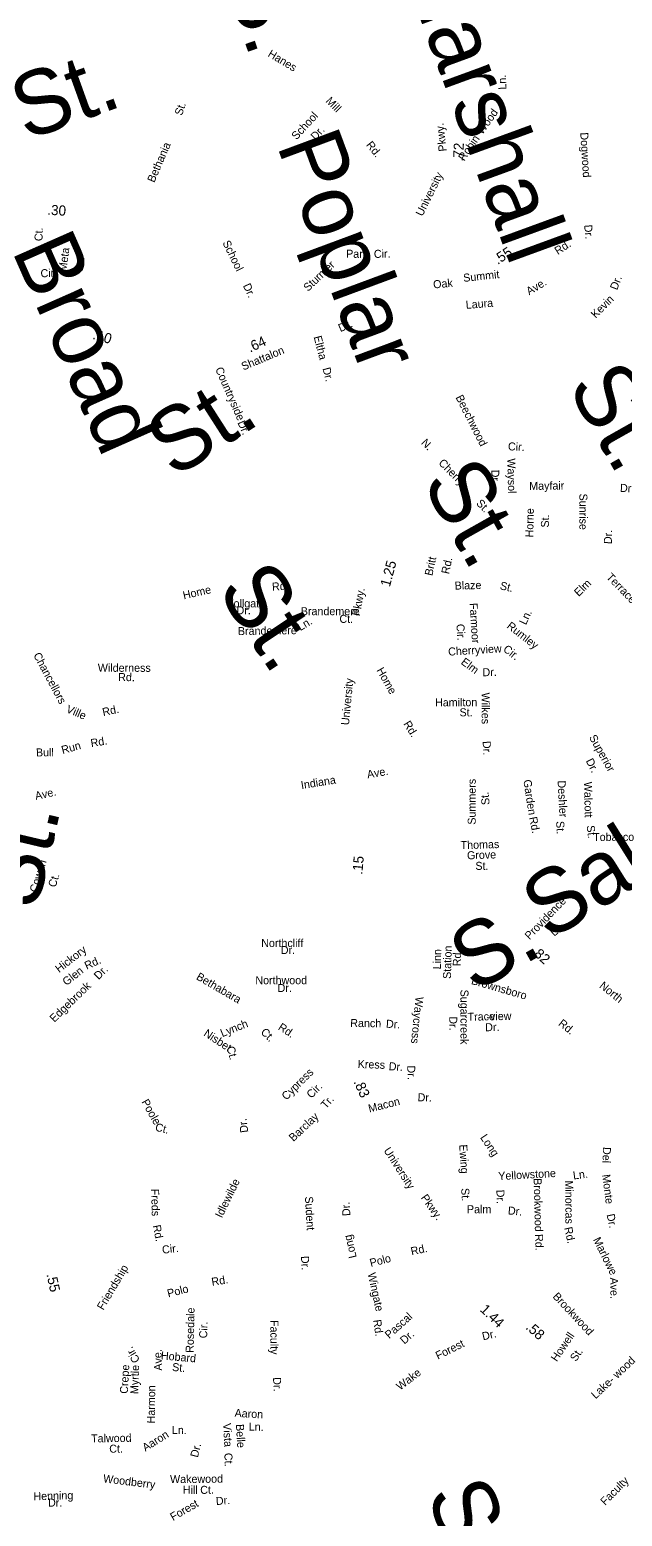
# Model space of a CAD drawing. Extents: x 1553981 to 1780076, y 812965 to 996873.
# Drawn here: x 1631790 to 1632669, y 849777 to 851982 of the extents above; entities that cross this region are included whole.
import ezdxf

# ---------------------------------------------------------------- set-up
doc = ezdxf.new("R2010")
doc.units = 0
for name, color, linetype in [('Exist Road Non-System Type 51 Label', 7, 'Continuous'), ('Exist Road Secondary Mileage Hundredths English Label', 7, 'Continuous'), ('Map Preparation Border Antique Large Shape', 7, 'Continuous')]:
    doc.layers.add(name, color=color, linetype=linetype)

msp = doc.modelspace()

# ---------------------------------------------------------------- texts
at = {"layer": 'Exist Road Non-System Type 51 Label'}
for s, height, rotation, p in [('Marshall', 95, 290.0731, (1632339.3, 852080.3)), ('S.', 95, 288.9209, (1632078.6, 852052.4)), ('St.', 95, 19.7887, (1631783.9, 851817.6)), ('Hanes', 11.88, 329.1772, (1632142.1, 851943.5)), ('Ln.', 11.88, 92.0969, (1632497.3, 851893.8)), ('Mill', 11.88, 314.3448, (1632228.2, 851875.9)), ('School', 11.88, 47.1963, (1632185.6, 851818.2)), ('Wood', 11.88, 54.5217, (1632461.4, 851826)), ('Poplar', 95, 290.3707, (1632155.9, 851811.4)), ('Dr.', 11.88, 47.1963, (1632214.1, 851817.6)), ('Robin', 11.88, 55.4105, (1632434.5, 851786.8)), ('Dogwood', 11.88, 273.5931, (1632606.7, 851829.8)), ('Rd.', 11.88, 308.572, (1632288.3, 851811.3)), ('Dr.', 11.88, 275.0819, (1632612.5, 851692.7)), ('Broad', 95, 293.8107, (1631762.5, 851655.3)), ('Ct.', 11.88, 88.6998, (1631808.7, 851668.7)), ('School', 11.88, 295.9309, (1632075.5, 851666.5)), ('Meta', 11.87, 82.6531, (1631844.2, 851623.4)), ('Park', 11.88, 358.6211, (1632259.2, 851644.4)), ('Cir.', 11.87, 1.352, (1632300.6, 851643.9)), ('Cir.', 11.88, 1.981, (1631806, 851615.1)), ('Dr.', 11.87, 82.6531, (1631868.6, 851623.9)), ('Sturmer', 11.87, 43.5499, (1632202.7, 851593.4)), ('Dr.', 11.88, 294.7328, (1632105.9, 851602.9)), ('Ave.', 11.88, 31.125, (1632531, 851588.3)), ('Dr.', 11.88, 68.9622, (1632661.4, 851595.4)), ('Laura', 11.88, 4.4816, (1632437.3, 851568.3)), ('Kevin', 11.88, 45.1038, (1632629.6, 851553.5)), ('Eltha', 11.88, 284.6129, (1632211, 851526.8)), ('Countryside', 11.875, 293.5159, (1632064.8, 851479)), ('Dr.', 11.88, 284.4327, (1632224.1, 851479.9)), ('St.', 95, 299.4456, (1632586.6, 851453.7)), ('St.', 95, 32.6529, (1632003.6, 851315.9)), ('Beechwood', 11.87, 296.8338, (1632421.4, 851437.1)), ('Dr.', 11.88, 293.5159, (1632097.8, 851399.6)), ('N.', 11.88, 313.7502, (1632369.8, 851368.8)), ('Cir.', 11.88, 357.2843, (1632499.3, 851358.6)), ('St.', 95, 299.3634, (1632370.8, 851311)), ('Cherry', 11.88, 314.6983, (1632395.6, 851338.8)), ('Waysol', 11.87, 271.3693, (1632498.5, 851346.4)), ('Dr.', 11.87, 271.3693, (1632474.7, 851329.6)), ('Mayfair', 11.88, 0.7722, (1632531.1, 851299.7)), ('Sunrise', 11.88, 270.0227, (1632605.5, 851294.3)), ('Dr.', 11.88, 356.8408, (1632665.5, 851297)), ('St.', 11.87, 313.7565, (1632451.5, 851279.1)), ('Horne', 11.88, 88.8359, (1632537, 851229.2)), ('St.', 11.88, 88.8359, (1632560.2, 851243.8)), ('Dr.', 11.88, 88.7027, (1632653.6, 851219.3)), ('St.', 95, 303.5775, (1632066.3, 851151.3)), ('Britt', 11.88, 77.8365, (1632387.2, 851171.6)), ('Rd.', 11.88, 77.8365, (1632411.9, 851174.2)), ('Rd.', 11.88, 3.9423, (1632149.7, 851150.2)), ('Blaze', 11.88, 1.3863, (1632420.5, 851151.8)), ('St.', 11.87, 346.8364, (1632486.8, 851152.5)), ('Elm', 11.88, 44.4001, (1632604.5, 851140.8)), ('Terrace', 11.88, 314.3249, (1632644.5, 851169.5)), ('Home', 11.88, 12.8534, (1632018.5, 851137.3)), ('Farmoor', 11.88, 273.585, (1632442.4, 851131.7)), ('Ln.', 11.88, 64.6535, (1632526.1, 851098.6)), ('Brandemere', 11.87, 0.9828, (1632098.8, 851084.3)), ('Ln.', 11.88, 31.008, (1632191.4, 851090.2)), ('Cir.', 11.88, 273.585, (1632422.9, 851100.6)), ('Rumley', 11.88, 321.912, (1632496.7, 851095.9)), ('Chancellors', 11.875, 298.1893, (1631794.7, 851054.7)), ('Cherryview', 11.88, 3.5763, (1632411.1, 851053.8)), ('Elm', 11.88, 323.5526, (1632428.7, 851042.3)), ('Cir.', 11.88, 321.912, (1632491.3, 851061.6)), ('Wilderness', 11.88, 359.9777, (1631890.8, 851029.9)), ('Rd.', 11.88, 359.4648, (1631921, 851016.2)), ('Home', 11.87, 299.2616, (1632304, 851032.3)), ('Dr.', 11.88, 1.2876, (1632461.8, 851023.3)), ('Hamilton', 11.88, 0.3871, (1632391.3, 850978.5)), ('Wilkes', 11.88, 270.1647, (1632460.4, 850999.1)), ('Ville', 11.88, 336.976, (1631842.9, 850970.2)), ('Rd.', 11.88, 11.9842, (1631898.9, 850964.1)), ('St.', 11.88, 359.8069, (1632427.6, 850963.9)), ('Rd.', 11.88, 302.2274, (1632343.8, 850952.6)), ('Run', 11.88, 15.5803, (1631838.6, 850907.8)), ('Rd.', 11.88, 9.4506, (1631881.1, 850918.1)), ('Dr.', 11.87, 272.1303, (1632462, 850927.1)), ('Superior', 11.88, 299.1661, (1632619.4, 850932.6)), ('Bull', 11.88, 0.6233, (1631799.1, 850904.3)), ('Dr.', 11.88, 296.9846, (1632614.6, 850897.8)), ('Ave.', 11.87, 9.867, (1632291.3, 850871.7)), ('Salem', 95, 32.0713, (1632560.3, 850629.9)), ('Ave.', 11.87, 12.215, (1631798.9, 850839.8)), ('Indiana', 11.88, 9.3345, (1632193.2, 850855.8)), ('Summers', 11.88, 89.9293, (1632451.6, 850803.1)), ('Garden', 11.88, 278.5777, (1632522.3, 850869.1)), ('Deshler', 11.88, 273.0208, (1632573.1, 850868.4)), ('Walcott', 11.87, 271.1338, (1632612.4, 850866.7)), ('St.', 11.88, 94.7168, (1632472.3, 850832.7)), ('St.', 95, 76.7191, (1631800.2, 850674.3)), ('Rd.', 11.88, 281.4454, (1632530.8, 850813.7)), ('St.', 11.88, 273.0208, (1632571, 850808.2)), ('St.', 11.88, 276.0666, (1632616.3, 850801.6)), ('Tobacco', 11.88, 0.1113, (1632625.9, 850778.9)), ('Thomas', 11.88, 1.7498, (1632429.4, 850766.7)), ('Grove', 11.87, 1.9621, (1632438.9, 850751.6)), ('Cowan', 11.88, 73.0536, (1631800.5, 850701.7)), ('St.', 11.88, 359.7356, (1632451.1, 850736.1)), ('Ct.', 11.88, 73.0536, (1631828.1, 850709.3)), ('Providence', 11.88, 46.0097, (1632531.5, 850631.7)), ('S.', 95, 29.4841, (1632449.3, 850553.1)), ('Ln.', 11.88, 43.5543, (1632568.4, 850636.7)), ('Hickory', 11.88, 37.6686, (1631833.3, 850582.9)), ('Linn', 11.88, 89.365, (1632400.1, 850588.4)), ('Station', 11.87, 88.4573, (1632414.8, 850574.2)), ('Rd.', 11.88, 88.2955, (1632429.4, 850593)), ('Glen', 11.88, 37.6686, (1631844, 850563.6)), ('Rd.', 11.88, 24.3572, (1631874.3, 850587.8)), ('Dr.', 11.88, 45.0238, (1631892, 850572.3)), ('Edgebrook', 11.88, 44.0894, (1631826.3, 850509.1)), ('Bethabara', 11.88, 329.7861, (1632035.8, 850574.3)), ('Brownsboro', 11.88, 343.9261, (1632444.1, 850566.9)), ('Waycross', 11.88, 264.3614, (1632362.4, 850548.2)), ('Sugarcreek', 11.88, 270, (1632429, 850558.4)), ('Trace', 11.88, 1.5706, (1632439.7, 850512)), ('-view', 11.88, 1.5706, (1632467.7, 850512.6)), ('Nisbet', 11.88, 326.378, (1632046.8, 850490.8)), ('Lynch', 11.88, 21.6817, (1632075.5, 850487.8)), ('Ct.', 11.88, 315.0536, (1632131.6, 850494.4)), ('Rd.', 11.88, 326.9359, (1632157.3, 850499.8)), ('Ranch', 11.88, 359.3395, (1632265.4, 850503)), ('Dr.', 11.88, 356.4137, (1632318.2, 850502)), ('Dr.', 11.88, 270, (1632412.4, 850518.8)), ('Dr.', 11.88, 1.5706, (1632465.8, 850496.6)), ('Rd.', 11.88, 321.093, (1632573.3, 850506.4)), ('Ct.', 11.88, 285.0324, (1632081.9, 850472.7)), ('Cypress', 11.88, 44.7704, (1632170.6, 850393.6)), ('Kress', 11.88, 358.0523, (1632276.3, 850442.2)), ('Dr.', 11.88, 355.8421, (1632322.2, 850439)), ('Dr.', 11.88, 272.8109, (1632349.8, 850445.6)), ('Cir.', 11.88, 44.7704, (1632207.6, 850396.2)), ('Poole', 11.88, 299.4574, (1631955.1, 850391.8)), ('Tr.', 11.88, 48.5515, (1632229.4, 850380.7)), ('Macon', 11.88, 13.9788, (1632293.8, 850376)), ('Dr.', 11.87, 358.3414, (1632365.3, 850392.9)), ('Barclay', 11.88, 43.2972, (1632181.1, 850332.2)), ('Ct.', 11.88, 345.9534, (1631975.1, 850349.3)), ('Dr.', 11.88, 97.7033, (1632114.2, 850346.9)), ('Ewing', 11.88, 273.6356, (1632427.1, 850328.3)), ('Long', 11.88, 303.4806, (1632457.7, 850339)), ('Del', 11.88, 267.9499, (1632640.5, 850325.1)), ('Yellowstone', 11.875, 3.1299, (1632485.4, 850275.8)), ('Ln.', 11.88, 7.333, (1632596.7, 850276.7)), ('Monte', 11.88, 277.2707, (1632639.2, 850283.6)), ('Freds', 11.87, 271.743, (1631969.8, 850262.7)), ('Idlewilde', 11.88, 63.9916, (1632074.9, 850218.7)), ('St.', 11.87, 273.6985, (1632430, 850263.6)), ('Dr.', 11.88, 271.889, (1632482.3, 850261.4)), ('Brookwood', 11.88, 271.4872, (1632537.5, 850278.5)), ('Minorcas', 11.87, 270.4993, (1632584.3, 850275.2)), ('Sudent', 11.87, 273.1563, (1632198.2, 850251.3)), ('Dr.', 11.88, 94.0847, (1632265.8, 850222.9)), ('Dr.', 11.88, 94.0847, (1632265.8, 850222.9)), ('Palm', 11.88, 359.9382, (1632438.6, 850226.7)), ('Dr.', 11.88, 354.9025, (1632499, 850225)), ('Dr.', 11.88, 281.9057, (1632645.8, 850224.5)), ('Rd.', 11.88, 281.3468, (1631972.2, 850208.2)), ('Long', 11.88, 103.4813, (1632275.1, 850161.4)), ('Rd.', 11.88, 272.1643, (1632539.6, 850195.6)), ('Rd.', 11.88, 282.3111, (1632582.9, 850205)), ('Marlowe', 11.88, 296.2202, (1632625.4, 850187.5)), ('Cir.', 11.88, 6.3242, (1631986.8, 850166.5)), ('Rd.', 11.88, 12.5206, (1632356.6, 850164.1)), ('Friendship', 11.88, 59.3908, (1631898.9, 850082)), ('Dr.', 11.88, 273.5264, (1632192.2, 850163)), ('Polo', 11.88, 14.4063, (1632296, 850146.9)), ('Rd.', 11.88, 9.5609, (1632060.5, 850118.8)), ('Wingate', 11.88, 282.3504, (1632291.2, 850137.1)), ('Ave.', 11.87, 271.2385, (1632651, 850131.2)), ('Polo', 11.88, 14.4537, (1631995.5, 850101.6)), ('Brookwood', 11.88, 313.1198, (1632565, 850102.4)), ('Rosedale', 11.87, 88.694, (1632032.9, 850019.5)), ('Pascal', 11.87, 41.9455, (1632323.2, 850039.8)), ('Cir.', 11.88, 88.513, (1632053, 850041)), ('Faculty', 11.88, 270.0081, (1632146.9, 850068.3)), ('Rd.', 11.88, 278.0148, (1632299.4, 850068.1)), ('Dr.', 11.87, 41.9455, (1632345.8, 850031.6)), ('Forest', 11.88, 26.453, (1632395.6, 850009.3)), ('Dr.', 11.88, 13.3882, (1632462.6, 850038)), ('Howell', 11.88, 55.8999, (1632572, 850005.5)), ('Cir.', 11.88, 120.4051, (1631953.9, 850008.7)), ('Ave.', 11.87, 91.6542, (1631986.2, 849993.3)), ('Hobard', 11.88, 354.998, (1631984.1, 850009.9)), ('St.', 11.88, 55.8999, (1632600.4, 850005.7)), ('Lake- wood', 11.88, 43.2531, (1632629.6, 849950.4)), ('Crepe', 11.88, 87.0067, (1631935.3, 849958.6)), ('Myrtle', 11.88, 88.2238, (1631950.8, 849958.2)), ('St.', 11.88, 354.998, (1632000.7, 849992.8)), ('Wake', 11.88, 37.4427, (1632339.4, 849963.3)), ('Harmon', 11.88, 89.3908, (1631975.5, 849914.8)), ('Dr.', 11.87, 273.1886, (1632150.7, 849983.1)), ('Aaron', 11.88, 356.5392, (1632093.5, 849924.7)), ('Ln.', 11.88, 359.3608, (1632000.7, 849899.2)), ('Vista', 11.88, 273.4986, (1632076.6, 849914.9)), ('Belle', 11.88, 273.4986, (1632095.7, 849913.5)), ('Ln.', 11.88, 358.3172, (1632114.6, 849904.3)), ('Talwood', 11.88, 0.8749, (1631880.9, 849886.6)), ('Ct.', 11.87, 0.3328, (1631907.8, 849871.4)), ('Aaron', 11.88, 32.0258, (1631961.4, 849872.8)), ('Dr.', 11.88, 75.7872, (1632039.2, 849863.5)), ('Ct.', 11.87, 272.3682, (1632078.5, 849870.9)), ('Woodberry', 11.88, 353.006, (1631898.2, 849827.5)), ('Wakewood', 11.87, 0.5589, (1631998.1, 849826.2)), ('Hill', 11.88, 359.3962, (1632016.9, 849810.5)), ('Ct.', 11.88, 1.0575, (1632042.9, 849810.2)), ('S.', 95, 291.6458, (1632377.6, 849809.8)), ('Faculty', 11.88, 45.0998, (1632643.6, 849792.4)), ('Henning', 11.88, 1.7039, (1631795.4, 849800.7)), ('Dr.', 11.87, 359.9641, (1631816.9, 849791.4)), ('Forest', 11.88, 30.0904, (1632002.4, 849769.9)), ('Dr.', 11.88, 4.1908, (1632066.4, 849793.7))]:
    msp.add_text(s, height=height, rotation=rotation, dxfattribs=at).set_placement(p)
for s, p in [('Tollgate', (1632082.6, 851125.5)), ('Dr.', (1632096.7, 851115.2)), ('Brandemere', (1632192, 851113.9)), ('Ct.', (1632249.4, 851102.5)), ('Northcliff', (1632133.3, 850621.6)), ('Dr.', (1632162.3, 850611.2)), ('Northwood', (1632124.6, 850566.4)), ('Dr.', (1632157.6, 850554.9))]:
    msp.add_text(s, height=11.88, dxfattribs=at).set_placement(p)
at = {"layer": 'Exist Road Secondary Mileage Hundredths English Label'}
for s, rotation, p in [('.72', 87.4072, (1632432.9, 851786.6)), ('.30', 356.5146, (1631815.4, 851708.1)), ('.55', 33.4435, (1632484.2, 851633.5)), ('.10', 343.9485, (1631882.2, 851523.9)), ('.64', 24.5204, (1632116.8, 851503.4)), ('1.25', 74.8646, (1632324.1, 851154.9)), ('.15', 85.2092, (1632283.3, 850728.4)), ('.82', 318.3729, (1632532.9, 850613.3)), ('.83', 294.4943, (1632270, 850421.7)), ('.55', 282.4529, (1631814.5, 850135.8)), ('1.44', 316.2346, (1632457, 850082.5)), ('.58', 318.523, (1632524.8, 850056))]:
    msp.add_text(s, height=15, rotation=rotation, dxfattribs=at).set_placement(p)
at = {"layer": 'Map Preparation Border Antique Large Shape'}
for s, height, rotation, p in [('St.', 11.87, 71.3851, (1632015.6, 851854.2)), ('Pkwy.', 11.87, 96.6054, (1632408.6, 851802.5)), ('Bethania', 11.88, 66.6022, (1631974.5, 851754.8)), ('University', 11.88, 63.6293, (1632372.5, 851704.8)), ('Rd.', 11.88, 33.4435, (1632573.5, 851648.1)), ('Summit', 11.87, 6.0838, (1632433.7, 851608.3)), ('Oak', 11.88, 5.1328, (1632389, 851598.6)), ('Dr.', 11.88, 23.537, (1632250.8, 851533.7)), ('Shattalon', 11.87, 22.7094, (1632106.8, 851476.8)), ('Pkwy.', 11.87, 79.2989, (1632279.5, 851112)), ('University', 11.88, 84.6335, (1632263.5, 850950.3)), ('North', 11.88, 321.1254, (1632634.2, 850562.3)), ('University', 11.87, 302.9, (1632314.5, 850319.7)), ('Pkwy.', 11.88, 305.4618, (1632369.6, 850249.6))]:
    msp.add_text(s, height=height, rotation=rotation, dxfattribs=at).set_placement(p)

doc.saveas('drawing.dxf')
